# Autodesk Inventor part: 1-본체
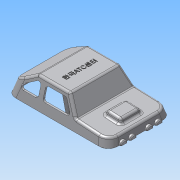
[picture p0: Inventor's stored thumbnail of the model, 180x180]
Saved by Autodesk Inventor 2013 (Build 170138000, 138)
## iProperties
Created: 2015-05
Part Number: 1-본체
Material: ABS 플라스틱
Document SubType Name: Modeling
Designer: Administrator
Density: 1.06 g/cm^3
Mass: 36.8459 g
Surface Area: 320.288 cm^2
Volume: 34.7603 cm^3
Author: Administrator
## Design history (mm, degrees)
sketch "스케치1"
  geometry: L1 (-61, 38)-(61, 38); L2 (61, 38)-(61, -38); L3 (61, -38)-(-61, -38); L4 (-61, -38)-(-61, 38); L5 (-61, 38)-(61, -38); L6 (61, 38)-(-61, -38); 1 further point
  constraints: 12 end point, 2 midpoint, 2 parallel, 1 horizontal, 1 perpendicular
  dimensions: "d0" = 122 distance of L2.end L3.end; "d2" = 76 distance of L1.end L2.end
extrude "돌출1" new body sketch "스케치1" distance "d3" = 30; taper "d4" = -15 deg
sketch "스케치2"
  geometry: L1 (52.962, 30)-(-52.962, 30) reference; L2 (-61, 0)-(-52.962, 30) reference; L3 (61, 0)-(52.962, 30) reference; L4 (-7.174, 30)-(-19, 11.075); L5 (-19, 11.075)-(-58.588, 9); L6 (61, 0)-(-61, 0) reference; L7 (61, 0)-(61, 28.689); L8 (31, 30)-(61, 11.254); L9 (57.378, 13.517)-(52.962, 30); 2 further points
  constraints: 10 end point, 6 point on line, 2 perpendicular, 1 coincident, 1 collinear
  dimensions: "d7" = 125 deg angle of L4 L5; "d10" = 42 horizontal distance of point (-61, 0) L4.end; "d11" = 9 vertical distance of point (-61, 0) L5.end; "d12" = 3 deg angle of L6 L5; "d13" = 30 horizontal distance of L8.start L8.end
extrude "돌출2" cut sketch "스케치2" stored distance "d14" = 30; taper "d15" = 0 deg
sketch "스케치3"
  geometry: L1 (-28.121, 48.588)-(-8.121, 48.588); L2 (-8.121, 48.588)-(-8.121, 22.588); L3 (-8.121, 22.588)-(-28.121, 22.588); L4 (-28.121, 22.588)-(-28.121, 48.588); L5 (-28.121, 48.588)-(-8.121, 22.588); L6 (-8.121, 48.588)-(-28.121, 22.588); L7 (2.879, 73.588)-(2.879, -2.412) reference; 3 further points
  constraints: 12 end point, 3 midpoint, 2 parallel, 1 horizontal, 1 horizontal alignment, 1 perpendicular
  dimensions: "d16" = 20 distance of L1.start L1.end; "d18" = 11 distance between parallel lines of L7 L2; "d19" = 26 distance of L1.end L2.end
extrude "돌출3" join sketch "스케치3" distance "d20" = 5; taper "d21" = -20 deg
fillet "모깎기4" dims "d95" = 3, "d104" = 12
fillet "모깎기7" dims "d105" = 3
feature "쉘1" dims "d30" = 2
sketch "스케치4"
  geometry: L1 (-5.284, 23.59)-(-10.908, 14.59); L2 (-8.364, 10)-(17.224, 10); L3 (20.224, 13)-(20.224, 22); L4 (17.224, 25)-(-2.74, 25); L5 (31, 30)-(-7.174, 30) reference; L6 (57.378, 13.517)-(31, 30) reference; L7 (-7.174, 30)-(-19, 11.075) reference; L8 (28.571, 10)-(43.109, 10); L9 (25.571, 13)-(25.571, 21.896); L10 (44.699, 15.544)-(30.321, 24.528); A1 r 3 centre (-2.74, 22) between (-2.74, 25) and (-5.284, 23.59); A2 r 3 centre (-8.364, 13) between (-10.908, 14.59) and (-8.364, 10); A3 r 3 centre (17.224, 13) between (17.224, 10) and (20.224, 13); A4 r 3 centre (28.571, 13) between (25.571, 13) and (28.571, 10); A5 r 3 centre (43.109, 13) between (43.109, 10) and (44.699, 15.544); A6 r 3 centre (17.224, 22) between (20.224, 22) and (17.224, 25); A7 r 3.104 centre (28.676, 21.896) between (30.321, 24.528) and (25.571, 21.896); 6 further points
  constraints: 14 end point, 14 point on circle, 14 tangent, 10 point on line, 7 centre point, 5 equal radius, 3 parallel, 3 perpendicular, 1 collinear, 1 horizontal
  dimensions: "d23" = 5 distance between parallel lines of L5 L4; "d24" = 5 distance between parallel lines of L7 L1; "d25" = 15 distance of point (20.224, 10) point (20.224, 25); "d26" = 34 distance of point (-13.776, 10) point (20.224, 10); "d29" = 28 distance of point (25.571, 10) point (53.571, 10); "d32" = 5 distance between parallel lines of L6 L10; "d34" = 3 radius of A1; "d35" = 3.1045 radius of A7
extrude "돌출4" cut sketch "스케치4" stored distance "d36" = 5; taper "d37" = 0 deg
node "작업 평면1"
sketch "스케치5"
  geometry: A1 r 4 centre (-10, 0) between (-6, 0) and (-14, 0); A2 r 4 centre (-21, 0) between (-17, 0) and (-25, 0); A3 r 4 centre (10, 0) between (14, 0) and (6, 0); A4 r 4 centre (21, 0) between (25, 0) and (17, 0); 7 further points
  constraints: 8 point on circle, 4 centre point, 3 equal radius, 13 other
  dimensions: "d39" = 4 radius of A4; "d41" = 20 distance of A3.centre A1.centre; "d42" = 11 distance of A4.centre A3.centre; "d43" = 11 distance of A1.centre A2.centre; "d44" = 10 distance of point (0, 0) A1.centre
extrude "돌출5" join sketch "스케치5" stored distance "d45" = 5; taper "d46" = 0 deg
sketch "스케치6"
  geometry: L1 (5, -21)-(-5, -21); L2 (-5, -21)-(-5, -23); L3 (-5, -23)-(5, -23); L4 (5, -23)-(5, -21); L5 (5, -21)-(-5, -23); L6 (-5, -21)-(5, -23); L7 (45, 1)-(35, 1); L8 (35, 1)-(35, -1); L9 (35, -1)-(45, -1); L10 (45, -1)-(45, 1); L11 (45, 1)-(35, -1); L12 (35, 1)-(45, -1); L13 (5, 23)-(-5, 23); L14 (-5, 23)-(-5, 21); L15 (-5, 21)-(5, 21); L16 (5, 21)-(5, 23); L17 (5, 23)-(-5, 21); L18 (-5, 23)-(5, 21); L19 (-35, 1)-(-45, 1); L20 (-45, 1)-(-45, -1); L21 (-45, -1)-(-35, -1); L22 (-35, -1)-(-35, 1); L23 (-35, 1)-(-45, -1); L24 (-45, 1)-(-35, -1); L25 (-61, -26.409)-(-61, 26.409) reference; L26 (49.409, -38)-(-49.409, -38) reference; 19 further points
  constraints: 48 end point, 15 midpoint, 8 parallel, 6 equal length, 4 horizontal, 4 perpendicular, 3 vertical alignment, 2 horizontal alignment
  dimensions: "d47" = 10 distance between parallel lines of L2 L4; "d49" = 2 distance of L3.end L1.start; "d50" = 44 distance of point (0, 22) point (0, -22); "d51" = 80 distance of point (-40, 0) point (40, 0); "d52" = 21 distance from line of L25 point (-40, 0); "d53" = 16 distance from line of L26 point (0, -22)
extrude "돌출6" join sketch "스케치6" stored distance "d54" = 5; taper "d55" = 0 deg
feature "면 기울기5" dims angle "d60" = 10 deg
feature "면 기울기6" dims angle "d61" = 10 deg
feature "면 기울기7" dims angle "d62" = 10 deg
feature "면 기울기8" dims angle "d63" = 10 deg
feature "면 기울기9" dims angle "d64" = 2.5 deg
feature "면 기울기10" dims angle "d65" = 2.5 deg
feature "면 기울기11" dims angle "d66" = 2.5 deg
feature "면 기울기12" dims angle "d67" = 2.5 deg
sketch "스케치7"
  geometry: L1 (-49.409, -38)-(49.409, -38) reference; C1 r 3 at (-40, 0); C2 r 3 at (0, -22); C3 r 3 at (40, 0); C4 r 3 at (0, 22); 5 further points
  constraints: 4 centre point, 3 equal radius, 2 horizontal alignment, 2 vertical alignment
  dimensions: "d68" = 6 diameter of C4; "d70" = 44 distance of C2.centre C4.centre; "d71" = 80 distance of C3.centre C1.centre; "d72" = 16 distance from line of L1 C2.centre; "d73" = 40 distance of point (0, 0) C1.centre
extrude "돌출7" join sketch "스케치7" stored distance "d74" = 5; taper "d75" = 4 deg
sketch "스케치8"
  geometry: L1 (-35, -1)-(-37.172, -1) reference; L2 (-35, 1)-(-35, -1) reference; L3 (-37.172, 1)-(-35, 1) reference; L4 (-45, 1)-(-42.828, 1) reference; L5 (-45, -1)-(-45, 1) reference; L6 (-42.828, -1)-(-45, -1) reference; L7 (-5, -21)-(-2.828, -21) reference; L8 (-5, -23)-(-5, -21) reference; L9 (-2.828, -23)-(-5, -23) reference; L10 (5, -23)-(2.828, -23) reference; L11 (5, -21)-(5, -23) reference; L12 (2.828, -21)-(5, -21) reference; L13 (35, 1)-(37.172, 1) reference; L14 (35, -1)-(35, 1) reference; L15 (37.172, -1)-(35, -1) reference; L16 (45, -1)-(42.828, -1) reference; L17 (45, 1)-(45, -1) reference; L18 (42.828, 1)-(45, 1) reference; A1 r 3 centre (0, 22) between (2.828, 23) and (-2.828, 23) reference; A2 r 3 centre (-40, 0) between (-37.172, 1) and (-42.828, 1) reference; A3 r 3 centre (-40, 0) between (-42.828, -1) and (-37.172, -1) reference; A4 r 3 centre (0, -22) between (-2.828, -23) and (2.828, -23) reference; A5 r 3 centre (0, -22) between (2.828, -21) and (-2.828, -21) reference; A6 r 3 centre (40, 0) between (37.172, -1) and (42.828, -1) reference; A7 r 3 centre (40, 0) between (42.828, 1) and (37.172, 1) reference; 5 further points
  constraints: 4 coincident
hole "구멍1" sketch "스케치8" at (-40, 0), (0, 22), (40, 0), (0, -22) diameter "d76" = 3.242; stored, may be unused: countersink angle "d80" = 90 deg, drill point angle "d82" = 118 deg; dims "d77" = 9, "d78" = 4, "d79" = 2, "d81" = 11
sketch "스케치9"
  geometry: L1 (31, 30)-(-7.174, 30) reference; L2 (-7.174, 30)-(-19, 11.075) reference; L3 (-19, 11.075)-(-19, 35.057); L4 (-19, 35.057)-(31, 35.057); L5 (31, 35.057)-(31, 30); L6 (-30.506, 10.472)-(-32.585, 15.37) reference; L7 (-32.585, 15.37)-(-19, 15.37); L8 (-30.506, 10.472)-(-19, 15.37); 1 further point
  constraints: 10 end point, 3 perpendicular, 1 parallel, 1 point on line
  dimensions: "d83" = 5.05695 distance between parallel lines of L1 L4
extrude "돌출8" cut sketch "스케치9" stored distance "d84" = 5; taper "d85" = 0 deg
sketch "스케치11"
  geometry: L1 (-61, -26.409)-(-61, 26.409) reference; 6 further points
  constraints: 1 horizontal alignment, 1 other
  dimensions: "d89" = 50 distance from line of L1 point (-11, 0)
feature "엠보싱1" sketch "스케치11" dims "d0" = 122, "d2" = 76, "d90" = 0.5, "d91" = 0
fillet "모깎기6" dims "d100" = 3
chamfer "모따기1" distance "d101" = 1; stored, may be unused: second distance "d102" = 2, angle "d103" = 45 deg
sketch "스케치13"
  geometry: L1 (58.929, 26.27)-(58.929, -26.27) reference; L2 (49.27, -35.929)-(-49.27, -35.929) reference; L3 (-58.929, -26.27)-(-58.929, 26.27) reference; L4 (-49.27, 35.929)-(49.27, 35.929) reference; L5 (49.27, 36.929)-(-49.27, 36.929); L6 (-59.929, 26.27)-(-59.929, -26.27); L7 (-49.27, -36.929)-(49.27, -36.929); L8 (59.929, -26.27)-(59.929, 26.27); 5 further points; 4 other entities
  constraints: 8 end point, 7 parallel, 16 other
  dimensions: "d106" = 1 distance between parallel lines of L8 L1
extrude "돌출11" join sketch "스케치13" distance "d107" = 1; taper "d108" = 0 deg
node "솔리드1"
node "투영된 루프1"
node "투영된 루프2"
node "투영된 루프3"
other parameters: "d38" = 63
